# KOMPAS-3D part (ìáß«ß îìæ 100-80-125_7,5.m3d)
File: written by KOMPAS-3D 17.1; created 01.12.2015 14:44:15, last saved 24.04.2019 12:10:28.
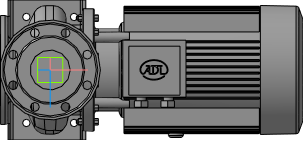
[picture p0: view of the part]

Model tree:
1. Операция без истории:2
